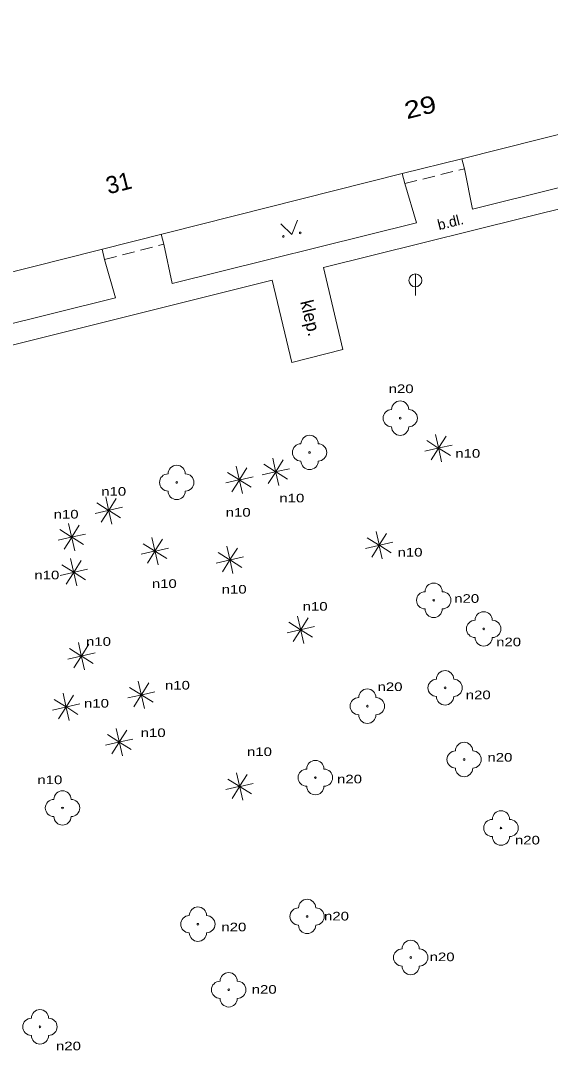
# Model space of a CAD drawing. Extents: x -670514 to -669423, y -1130798 to -1130123.
# Drawn here: x -669895.6 to -669864.8, y -1130649 to -1130589.1 of the extents above; entities that cross this region are included whole.
import ezdxf
from ezdxf.enums import TextEntityAlignment as Align

# ---------------------------------------------------------------- set-up
doc = ezdxf.new("R2010")
doc.units = 0
doc.header["$LTSCALE"] = 0.24
doc.linetypes.add('MEDIUM_DASHED', pattern=[4.5, 3, -1.5])
for name, color, linetype, lineweight in [('10', 7, 'Continuous', 13), ('22', 7, 'Continuous', 13), ('27', 7, 'Continuous', 13), ('36', 7, 'Continuous', 13), ('5', 7, 'Continuous', 13)]:
    doc.layers.add(name, color=color, linetype=linetype, lineweight=lineweight)
for name, color, linetype in [('40', 7, 'Continuous'), ('42', 7, 'Continuous'), ('44', 7, 'Continuous'), ('47', 7, 'Continuous')]:
    doc.layers.add(name, color=color, linetype=linetype)

msp = doc.modelspace()

# ---------------------------------------------------------------- linework, layer by layer
at = {"layer": '10'}
for p, q in [((-669845.694, -1130595.44), (-669878.012, -1130603.465)), ((-669873.281, -1130598.595), (-669872.594, -1130600.876)), ((-669872.594, -1130600.876), (-669886.809, -1130604.4)), ((-669887.296, -1130602.114), (-669886.809, -1130604.4)), ((-669890.738, -1130603.002), (-669890.1, -1130605.226)), ((-669878.012, -1130603.465), (-669876.878, -1130608.238)), ((-669879.859, -1130608.986), (-669876.878, -1130608.238))]:
    msp.add_line(p, q, dxfattribs=at)
for points in [[(-669869.812, -1130597.726), (-669869.347, -1130600.077), (-669854.71, -1130596.441)], [(-669934.206, -1130614.54), (-669932.249, -1130614.211), (-669931.868, -1130617.218), (-669928.189, -1130616.795), (-669928.585, -1130613.788), (-669911.245, -1130611.765), (-669880.993, -1130604.213), (-669879.859, -1130608.986)], [(-669890.1, -1130605.226), (-669904.32, -1130608.757), (-669904.788, -1130606.523)]]:
    msp.add_lwpolyline(points, dxfattribs=at)
at = {"layer": '22'}
for p, q in [((-669871.353, -1130613.944), (-669872.009, -1130613.53)), ((-669871.327, -1130613.924), (-669871.499, -1130613.17)), ((-669870.885, -1130613.274), (-669871.299, -1130613.93)), ((-669872.113, -1130614.144), (-669871.359, -1130613.972)), ((-669871.339, -1130613.998), (-669871.753, -1130614.654)), ((-669871.311, -1130614.004), (-669871.139, -1130614.758)), ((-669870.629, -1130614.398), (-669871.285, -1130613.984)), ((-669871.279, -1130613.956), (-669870.525, -1130613.784)), ((-669880.792, -1130615.299), (-669880.964, -1130614.545)), ((-669880.35, -1130614.649), (-669880.764, -1130615.305)), ((-669882.936, -1130615.788), (-669883.592, -1130615.374)), ((-669882.91, -1130615.768), (-669883.082, -1130615.014)), ((-669882.468, -1130615.118), (-669882.882, -1130615.774)), ((-669881.578, -1130615.519), (-669880.824, -1130615.347)), ((-669880.818, -1130615.319), (-669881.474, -1130614.905)), ((-669880.804, -1130615.373), (-669881.218, -1130616.029)), ((-669880.094, -1130615.773), (-669880.75, -1130615.359)), ((-669880.744, -1130615.331), (-669879.99, -1130615.159)), ((-669883.696, -1130615.988), (-669882.942, -1130615.816)), ((-669882.922, -1130615.842), (-669883.336, -1130616.498)), ((-669882.894, -1130615.848), (-669882.722, -1130616.602)), ((-669882.212, -1130616.242), (-669882.868, -1130615.828)), ((-669882.862, -1130615.8), (-669882.108, -1130615.628)), ((-669880.776, -1130615.379), (-669880.604, -1130616.133)), ((-669890.53, -1130617.561), (-669891.186, -1130617.147)), ((-669890.504, -1130617.541), (-669890.676, -1130616.787)), ((-669890.062, -1130616.891), (-669890.476, -1130617.547)), ((-669891.29, -1130617.761), (-669890.536, -1130617.589)), ((-669890.516, -1130617.615), (-669890.93, -1130618.271)), ((-669890.488, -1130617.621), (-669890.316, -1130618.375)), ((-669889.806, -1130618.015), (-669890.462, -1130617.601)), ((-669890.456, -1130617.573), (-669889.702, -1130617.401)), ((-669892.657, -1130619.097), (-669892.829, -1130618.343)), ((-669892.683, -1130619.117), (-669893.339, -1130618.703)), ((-669892.215, -1130618.447), (-669892.629, -1130619.103)), ((-669892.609, -1130619.129), (-669891.855, -1130618.957)), ((-669874.781, -1130619.568), (-669874.953, -1130618.814)), ((-669874.339, -1130618.918), (-669874.753, -1130619.574)), ((-669893.443, -1130619.317), (-669892.689, -1130619.145)), ((-669892.669, -1130619.171), (-669893.083, -1130619.827)), ((-669892.641, -1130619.177), (-669892.469, -1130619.931)), ((-669891.959, -1130619.571), (-669892.615, -1130619.157)), ((-669887.845, -1130619.931), (-669888.501, -1130619.517)), ((-669887.819, -1130619.911), (-669887.991, -1130619.157)), ((-669887.377, -1130619.261), (-669887.791, -1130619.917)), ((-669874.807, -1130619.588), (-669875.463, -1130619.174)), ((-669874.733, -1130619.6), (-669873.979, -1130619.428)), ((-669888.605, -1130620.131), (-669887.851, -1130619.959)), ((-669887.831, -1130619.985), (-669888.245, -1130620.641)), ((-669887.803, -1130619.991), (-669887.631, -1130620.745)), ((-669887.121, -1130620.385), (-669887.777, -1130619.971)), ((-669887.771, -1130619.943), (-669887.017, -1130619.771)), ((-669883.487, -1130620.441), (-669884.143, -1130620.027)), ((-669883.461, -1130620.421), (-669883.633, -1130619.667)), ((-669883.019, -1130619.771), (-669883.433, -1130620.427)), ((-669875.567, -1130619.788), (-669874.813, -1130619.616)), ((-669874.793, -1130619.642), (-669875.207, -1130620.298)), ((-669874.765, -1130619.648), (-669874.593, -1130620.402)), ((-669874.083, -1130620.042), (-669874.739, -1130619.628)), ((-669892.57, -1130621.158), (-669893.226, -1130620.744)), ((-669892.544, -1130621.138), (-669892.716, -1130620.384)), ((-669892.102, -1130620.488), (-669892.516, -1130621.144)), ((-669884.247, -1130620.641), (-669883.493, -1130620.469)), ((-669883.473, -1130620.495), (-669883.887, -1130621.151)), ((-669883.445, -1130620.501), (-669883.273, -1130621.255)), ((-669882.763, -1130620.895), (-669883.419, -1130620.481)), ((-669883.413, -1130620.453), (-669882.659, -1130620.281)), ((-669893.33, -1130621.358), (-669892.576, -1130621.186)), ((-669892.556, -1130621.212), (-669892.97, -1130621.868)), ((-669892.528, -1130621.218), (-669892.356, -1130621.972)), ((-669891.846, -1130621.612), (-669892.502, -1130621.198)), ((-669892.496, -1130621.17), (-669891.742, -1130620.998)), ((-669879.342, -1130624.475), (-669879.514, -1130623.721)), ((-669879.368, -1130624.495), (-669880.024, -1130624.081)), ((-669878.9, -1130623.825), (-669879.314, -1130624.481)), ((-669879.294, -1130624.507), (-669878.54, -1130624.335)), ((-669880.128, -1130624.695), (-669879.374, -1130624.523)), ((-669879.354, -1130624.549), (-669879.768, -1130625.205)), ((-669879.326, -1130624.555), (-669879.154, -1130625.309)), ((-669878.644, -1130624.949), (-669879.3, -1130624.535)), ((-669892.094, -1130626.006), (-669892.266, -1130625.252)), ((-669891.652, -1130625.356), (-669892.066, -1130626.012)), ((-669892.88, -1130626.226), (-669892.126, -1130626.054)), ((-669892.12, -1130626.026), (-669892.776, -1130625.612)), ((-669892.106, -1130626.08), (-669892.52, -1130626.736)), ((-669892.078, -1130626.086), (-669891.906, -1130626.84)), ((-669891.396, -1130626.48), (-669892.052, -1130626.066)), ((-669892.046, -1130626.038), (-669891.292, -1130625.866)), ((-669888.637, -1130628.283), (-669889.293, -1130627.869)), ((-669888.611, -1130628.263), (-669888.783, -1130627.509)), ((-669888.169, -1130627.613), (-669888.583, -1130628.269)), ((-669892.985, -1130628.966), (-669893.157, -1130628.212)), ((-669892.543, -1130628.316), (-669892.957, -1130628.972)), ((-669889.397, -1130628.483), (-669888.643, -1130628.311)), ((-669888.623, -1130628.337), (-669889.037, -1130628.993)), ((-669888.595, -1130628.343), (-669888.423, -1130629.097)), ((-669887.913, -1130628.737), (-669888.569, -1130628.323)), ((-669888.563, -1130628.295), (-669887.809, -1130628.123)), ((-669893.771, -1130629.186), (-669893.017, -1130629.014)), ((-669893.011, -1130628.986), (-669893.667, -1130628.572)), ((-669892.997, -1130629.04), (-669893.411, -1130629.696)), ((-669892.969, -1130629.046), (-669892.797, -1130629.8)), ((-669892.287, -1130629.44), (-669892.943, -1130629.026)), ((-669892.937, -1130628.998), (-669892.183, -1130628.826)), ((-669889.892, -1130631.008), (-669890.064, -1130630.254)), ((-669889.918, -1130631.028), (-669890.574, -1130630.614)), ((-669889.45, -1130630.358), (-669889.864, -1130631.014)), ((-669889.844, -1130631.04), (-669889.09, -1130630.868)), ((-669890.678, -1130631.228), (-669889.924, -1130631.056)), ((-669889.904, -1130631.082), (-669890.318, -1130631.738)), ((-669889.876, -1130631.088), (-669889.704, -1130631.842)), ((-669889.194, -1130631.482), (-669889.85, -1130631.068)), ((-669882.921, -1130633.607), (-669883.577, -1130633.193)), ((-669882.895, -1130633.587), (-669883.067, -1130632.833)), ((-669882.453, -1130632.937), (-669882.867, -1130633.593)), ((-669883.681, -1130633.807), (-669882.927, -1130633.635)), ((-669882.907, -1130633.661), (-669883.321, -1130634.317)), ((-669882.879, -1130633.667), (-669882.707, -1130634.421)), ((-669882.197, -1130634.061), (-669882.853, -1130633.647)), ((-669882.847, -1130633.619), (-669882.093, -1130633.447))]:
    msp.add_line(p, q, dxfattribs=at)
for centre, radius in [((-669873.549, -1130612.224), 0.05), ((-669878.818, -1130614.214), 0.05), ((-669871.319, -1130613.964), 0.04), ((-669880.784, -1130615.339), 0.04), ((-669886.545, -1130615.959), 0.05), ((-669882.902, -1130615.808), 0.04), ((-669890.496, -1130617.581), 0.04), ((-669892.649, -1130619.137), 0.04), ((-669887.811, -1130619.951), 0.04), ((-669874.773, -1130619.608), 0.04), ((-669883.453, -1130620.461), 0.04), ((-669892.536, -1130621.178), 0.04), ((-669871.601, -1130622.808), 0.05), ((-669879.334, -1130624.515), 0.04), ((-669868.694, -1130624.47), 0.05), ((-669892.086, -1130626.046), 0.04), ((-669870.939, -1130627.896), 0.05), ((-669888.603, -1130628.303), 0.04), ((-669892.977, -1130629.006), 0.04), ((-669875.46, -1130628.959), 0.05), ((-669889.884, -1130631.048), 0.04), ((-669869.834, -1130632.058), 0.05), ((-669878.483, -1130633.112), 0.05), ((-669882.887, -1130633.627), 0.04), ((-669893.186, -1130634.875), 0.05), ((-669867.688, -1130636.04), 0.05), ((-669885.312, -1130641.63), 0.05), ((-669878.963, -1130641.179), 0.05), ((-669872.939, -1130643.565), 0.05), ((-669883.523, -1130645.442), 0.05), ((-669894.498, -1130647.593), 0.05)]:
    msp.add_circle(centre, radius, dxfattribs=at)
for centre, start, end in [((-669874.049, -1130612.224), 90, 270), ((-669873.549, -1130611.724), 0, 180), ((-669873.049, -1130612.224), 270, 90), ((-669873.549, -1130612.724), 180, 0), ((-669878.818, -1130613.714), 0, 180), ((-669879.318, -1130614.214), 90, 270), ((-669878.318, -1130614.214), 270, 90), ((-669878.818, -1130614.714), 180, 0), ((-669886.545, -1130615.459), 0, 180), ((-669887.045, -1130615.959), 90, 270), ((-669886.045, -1130615.959), 270, 90), ((-669886.545, -1130616.459), 180, 0), ((-669871.601, -1130622.308), 0, 180), ((-669872.101, -1130622.808), 90, 270), ((-669871.101, -1130622.808), 270, 90), ((-669871.601, -1130623.308), 180, 0), ((-669868.694, -1130623.97), 0, 180), ((-669869.194, -1130624.47), 90, 270), ((-669868.194, -1130624.47), 270, 90), ((-669868.694, -1130624.97), 180, 0), ((-669870.939, -1130627.396), 0, 180), ((-669871.439, -1130627.896), 90, 270), ((-669870.439, -1130627.896), 270, 90), ((-669875.96, -1130628.959), 90, 270), ((-669875.46, -1130628.459), 0, 180), ((-669874.96, -1130628.959), 270, 90), ((-669870.939, -1130628.396), 180, 0), ((-669875.46, -1130629.459), 180, 0), ((-669869.834, -1130631.558), 0, 180), ((-669878.483, -1130632.612), 0, 180), ((-669870.334, -1130632.058), 90, 270), ((-669869.334, -1130632.058), 270, 90), ((-669878.983, -1130633.112), 90, 270), ((-669877.983, -1130633.112), 270, 90), ((-669869.834, -1130632.558), 180, 0), ((-669893.186, -1130634.375), 0, 180), ((-669878.483, -1130633.612), 180, 0), ((-669893.686, -1130634.875), 90, 270), ((-669892.686, -1130634.875), 270, 90), ((-669867.688, -1130635.54), 0, 180), ((-669893.186, -1130635.375), 180, 0), ((-669868.188, -1130636.04), 90, 270), ((-669867.188, -1130636.04), 270, 90), ((-669867.688, -1130636.54), 180, 0), ((-669878.963, -1130640.679), 0, 180), ((-669885.312, -1130641.13), 0, 180), ((-669879.463, -1130641.179), 90, 270), ((-669878.463, -1130641.179), 270, 90), ((-669885.812, -1130641.63), 90, 270), ((-669884.812, -1130641.63), 270, 90), ((-669878.963, -1130641.679), 180, 0), ((-669885.312, -1130642.13), 180, 0), ((-669872.939, -1130643.065), 0, 180), ((-669873.439, -1130643.565), 90, 270), ((-669872.439, -1130643.565), 270, 90), ((-669872.939, -1130644.065), 180, 0), ((-669883.523, -1130644.942), 0, 180), ((-669884.023, -1130645.442), 90, 270), ((-669883.023, -1130645.442), 270, 90), ((-669883.523, -1130645.942), 180, 0), ((-669894.998, -1130647.593), 90, 270), ((-669894.498, -1130647.093), 0, 180), ((-669893.998, -1130647.593), 270, 90), ((-669894.498, -1130648.093), 180, 0)]:
    msp.add_arc(centre, 0.5, start, end, dxfattribs=at)
at = {"layer": '27'}
msp.add_line((-669872.664, -1130603.842), (-669872.664, -1130605.092), dxfattribs=at)
msp.add_circle((-669872.6636, -1130604.2171), 0.375, dxfattribs=at)
at = {"layer": '36'}
msp.add_lwpolyline([(-669880.496, -1130600.927), (-669879.853, -1130601.559), (-669879.517, -1130600.722)], dxfattribs=at)
for centre in [(-669880.3421, -1130601.6612), (-669879.3634, -1130601.4559)]:
    msp.add_circle(centre, 0.05, dxfattribs=at)
at = {"layer": '5'}
for p, q in [((-669869.959, -1130597.144), (-669869.812, -1130597.726)), ((-669904.935, -1130605.941), (-669873.428, -1130598.013)), ((-669873.428, -1130598.013), (-669873.281, -1130598.595)), ((-669887.441, -1130601.539), (-669887.296, -1130602.114)), ((-669890.888, -1130602.406), (-669890.738, -1130603.002))]:
    msp.add_line(p, q, dxfattribs=at)
at = {"layer": '5', "linetype": 'MEDIUM_DASHED'}
for p, q in [((-669873.281, -1130598.595), (-669869.812, -1130597.726)), ((-669890.738, -1130603.002), (-669887.296, -1130602.114))]:
    msp.add_line(p, q, dxfattribs=at)
at = {"layer": '5'}
msp.add_lwpolyline([(-669873.428, -1130598.013), (-669869.959, -1130597.144), (-669838.065, -1130589.12)], dxfattribs=at)

# ---------------------------------------------------------------- texts
at = {"layer": '40'}
msp.add_text('b.dl.', height=0.6, rotation=13.945, dxfattribs=at).set_placement((-669870.5548, -1130601.1174), align=Align.CENTER)
at = {"layer": '42'}
msp.add_text('klep.', height=0.75, rotation=283.484, dxfattribs=at).set_placement((-669879.1221, -1130606.4906), align=Align.CENTER)
at = {"layer": '44', "width": 1.25}
msp.add_text('29', height=1, rotation=14.063, dxfattribs=at).set_placement((-669872.2615, -1130594.6284), align=Align.CENTER)
at = {"layer": '44'}
msp.add_text('31', height=1, rotation=14.124, dxfattribs=at).set_placement((-669889.7985, -1130599.0385), align=Align.CENTER)
at = {"layer": '47', "width": 1.3}
for s, p in [('n20', (-669873.4965, -1130610.765)), ('n10', (-669869.6215, -1130614.522)), ('n10', (-669890.2105, -1130616.73)), ('n10', (-669879.8505, -1130617.117)), ('n10', (-669892.9775, -1130618.055)), ('n10', (-669882.9705, -1130617.945)), ('n10', (-669872.9775, -1130620.264)), ('n10', (-669894.0965, -1130621.589)), ('n10', (-669887.2675, -1130622.086)), ('n10', (-669883.2055, -1130622.417)), ('n20', (-669869.6825, -1130622.954)), ('n10', (-669878.4965, -1130623.411)), ('n10', (-669891.0935, -1130625.453)), ('n20', (-669867.2435, -1130625.478)), ('n10', (-669886.5025, -1130627.993)), ('n20', (-669874.1405, -1130628.081)), ('n10', (-669891.2115, -1130629.042)), ('n20', (-669869.0095, -1130628.554)), ('n10', (-669887.9155, -1130630.754)), ('n10', (-669881.7345, -1130631.858)), ('n20', (-669867.7485, -1130632.183)), ('n10', (-669893.9225, -1130633.491)), ('n20', (-669876.4955, -1130633.445)), ('n20', (-669866.1505, -1130636.995)), ('n20', (-669877.2525, -1130641.412)), ('n20', (-669883.2235, -1130642.043)), ('n20', (-669871.1125, -1130643.778)), ('n20', (-669881.4575, -1130645.671)), ('n20', (-669892.8415, -1130648.957))]:
    msp.add_text(s, height=0.5, dxfattribs=at).set_placement(p, align=Align.CENTER)

doc.saveas('drawing.dxf')
